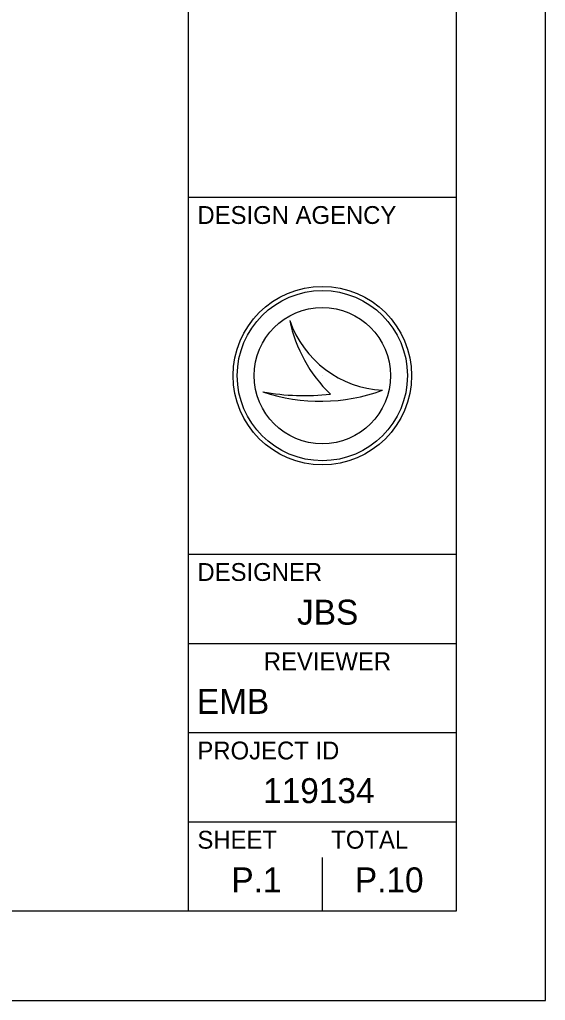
# Model space of a CAD drawing. Extents: x 0 to 34, y 0 to 22.
# Drawn here: x 31.05 to 34, y 0 to 5.49 of the extents above; entities that cross this region are included whole.
import ezdxf

# ---------------------------------------------------------------- set-up
doc = ezdxf.new("R2010")
doc.units = 0
for name, color, linetype in [('SH_Border', 7, 'Continuous'), ('SH_Cut_Line', 7, 'Continuous'), ('SH_Data', 7, 'Continuous')]:
    doc.layers.add(name, color=color, linetype=linetype)

msp = doc.modelspace()

# ---------------------------------------------------------------- linework, layer by layer
at = {"layer": 'SH_Border'}
for p, q in [((32, 0.5), (32, 21.5)), ((32, 4.5), (33.5, 4.5)), ((32, 2.5), (33.5, 2.5)), ((32, 2), (33.5, 2)), ((32, 1.5), (33.5, 1.5)), ((32, 1), (33.5, 1))]:
    msp.add_line(p, q, dxfattribs=at)
msp.add_lwpolyline([(1.5, 21.5), (33.5, 21.5), (33.5, 0.5), (1.5, 0.5)], close=True, dxfattribs=at)
at = {"layer": 'SH_Cut_Line'}
msp.add_lwpolyline([(0, 0), (34, 0), (34, 22), (0, 22)], close=True, dxfattribs=at)
at = {"layer": 'SH_Data'}
for p, q in [((32.5674, 3.8096), (32.5675, 3.8096)), ((32.75, 3.5), (32.75, 3.5)), ((32.4172, 3.4095), (32.4172, 3.4095)), ((33.0873, 3.4185), (33.0873, 3.4185)), ((32.75, 0.5), (32.75, 0.8)), ((32.375, 0.675), (32.375, 0.675))]:
    msp.add_line(p, q, dxfattribs=at)
for radius in [0.5, 0.4768, 0.4768, 0.3822]:
    msp.add_circle((32.75, 3.5), radius, dxfattribs=at)
for centre, radius, start, end in [((33.1159, 3.9976), 0.5798, 198.9257, 198.9319), ((33.3467, 3.9701), 0.7956, 191.6379, 191.6421), ((33.1159, 3.9976), 0.5798, 198.9319, 267.1657), ((33.3467, 3.9701), 0.7956, 191.6421, 226.0947), ((32.7394, 4.37), 1.0131, 251.4576, 290.0832), ((32.648, 4.6543), 1.2661, 259.4964, 259.4995), ((32.7394, 4.37), 1.0131, 251.4527, 251.4576), ((32.648, 4.6543), 1.2661, 259.4995, 276.6672)]:
    msp.add_arc(centre, radius, start, end, dxfattribs=at)

# ---------------------------------------------------------------- texts
for s, height, p in [('DESIGN AGENCY', 0.1, (32.05, 4.35)), ('DESIGNER', 0.1, (32.05, 2.35)), ('JBS', 0.14, (32.6082, 2.105)), ('REVIEWER', 0.1, (32.4218, 1.85)), ('EMB', 0.14, (32.0466, 1.605)), ('PROJECT ID', 0.1, (32.05, 1.35)), ('119134', 0.14, (32.4179, 1.105)), ('SHEET', 0.1, (32.05, 0.85)), ('TOTAL', 0.1, (32.8, 0.85)), ('P.1', 0.14, (32.2403, 0.605)), ('P.10', 0.14, (32.9322, 0.605))]:
    msp.add_text(s, height=height, dxfattribs=at).set_placement(p)

doc.saveas('drawing.dxf')
